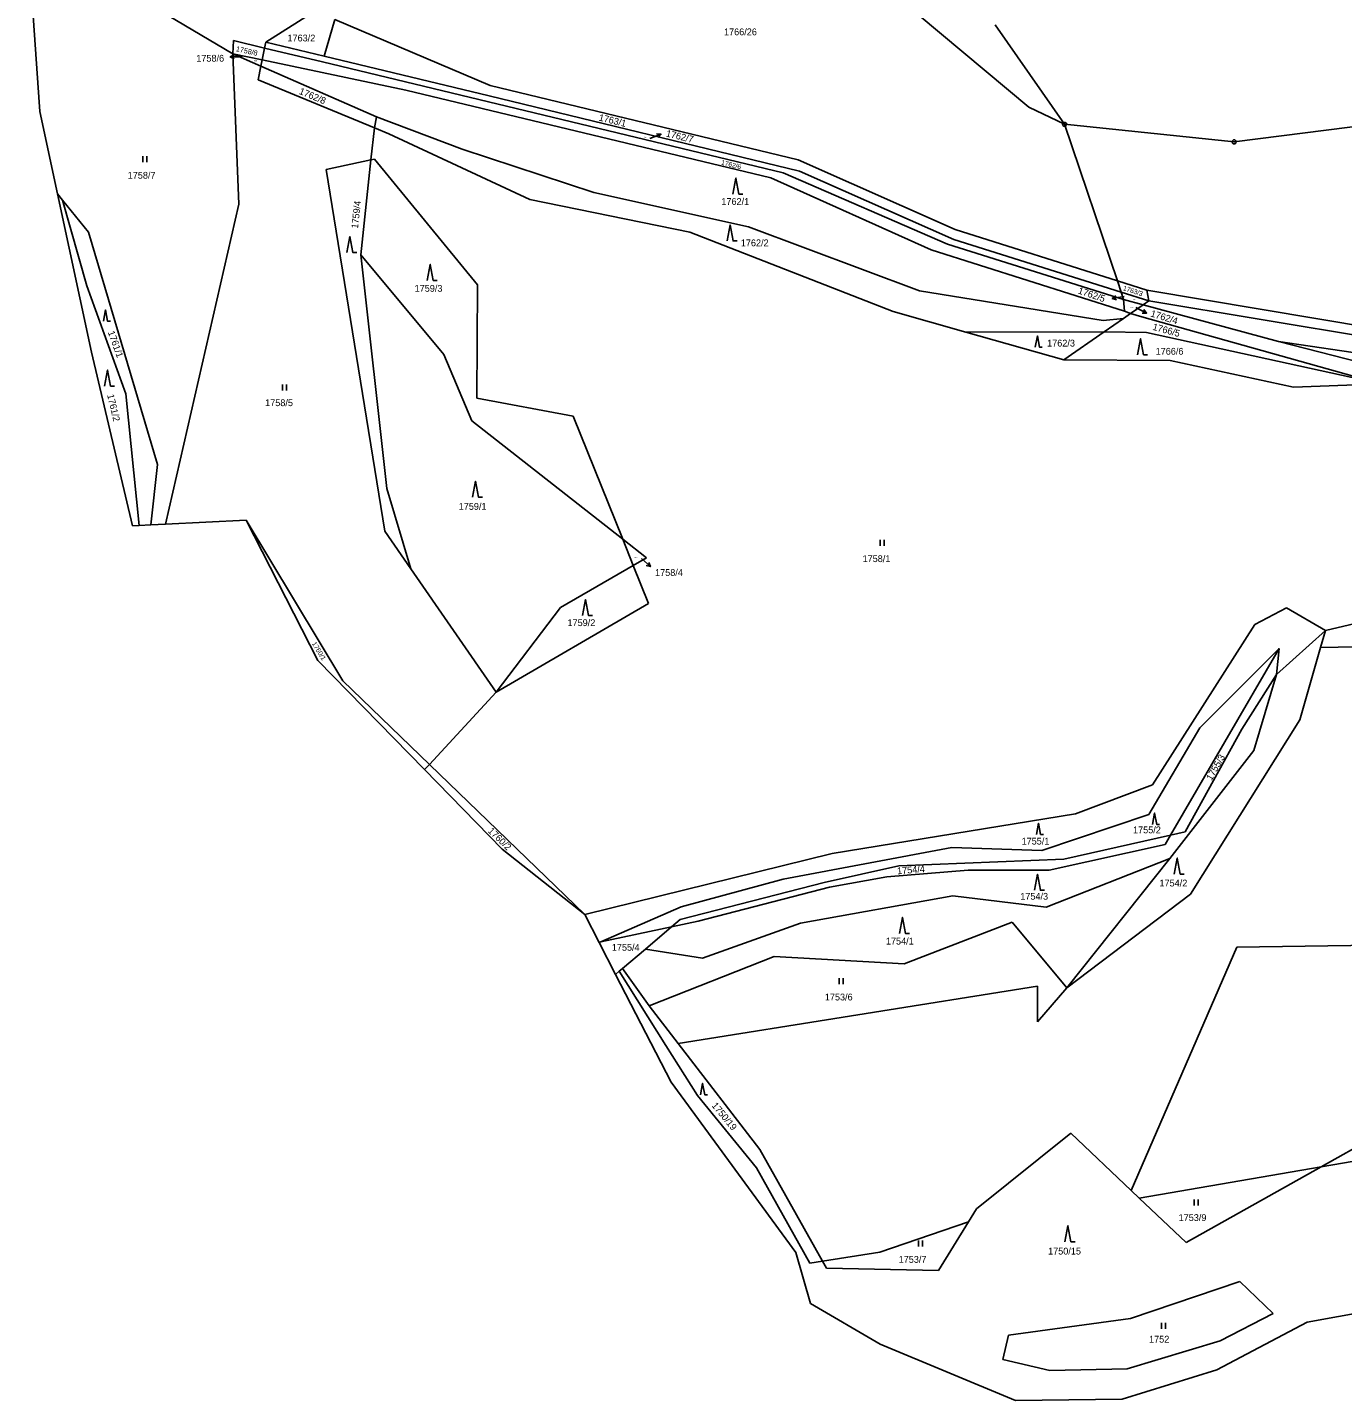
# Model space of a CAD drawing. Extents: x -609861 to -605046, y -1120287 to -1116307.
# Drawn here: x -609664.9 to -609336.2, y -1119535.1 to -1119191.9 of the extents above; entities that cross this region are included whole.
import ezdxf

# ---------------------------------------------------------------- set-up
doc = ezdxf.new("R2010")
doc.units = 0
for name, color, linetype in [('Vrstva 1', 7, 'Continuous'), ('Vrstva 2', 7, 'Continuous'), ('Vrstva 3', 7, 'Continuous'), ('Vrstva 7', 7, 'Continuous'), ('Vrstva 8', 7, 'Continuous')]:
    doc.layers.add(name, color=color, linetype=linetype)

msp = doc.modelspace()

# ---------------------------------------------------------------- linework, layer by layer
at = {"layer": 'Vrstva 1'}
for p, q in [((-609661.8, -1119212.92), (-609664.92, -1119167.98)), ((-609664.92, -1119167.98), (-609613.63, -1119198.48)), ((-609414.64, -1119211.82), (-609448.53, -1119183.44)), ((-609593.12, -1119187.81), (-609605.38, -1119195.59)), ((-609590.8, -1119199.1), (-609588.13, -1119189.92)), ((-609549.24, -1119206.37), (-609588.13, -1119189.92)), ((-609405.72, -1119216.1), (-609423.04, -1119191.27)), ((-609613.63, -1119198.48), (-609613.45, -1119195.16)), ((-609613.45, -1119195.16), (-609605.68, -1119197.03)), ((-609605.68, -1119197.03), (-609606.29, -1119200.02)), ((-609605.38, -1119195.59), (-609605.68, -1119197.03)), ((-609605.68, -1119197.03), (-609591.21, -1119200.52)), ((-609605.38, -1119195.59), (-609590.8, -1119199.1)), ((-609606.29, -1119200.02), (-609613.63, -1119198.48)), ((-609612.13, -1119236.03), (-609613.63, -1119198.48)), ((-609606.6, -1119201.55), (-609613.63, -1119198.48)), ((-609606.6, -1119201.55), (-609607.3, -1119204.98)), ((-609606.29, -1119200.02), (-609606.6, -1119201.55)), ((-609577.66, -1119214.2), (-609606.6, -1119201.55)), ((-609570.38, -1119207.57), (-609606.29, -1119200.02)), ((-609591.21, -1119200.52), (-609476.03, -1119228.22)), ((-609590.8, -1119199.1), (-609549.53, -1119209.02)), ((-609607.3, -1119204.98), (-609578.22, -1119216.98)), ((-609479.1, -1119229.5), (-609570.38, -1119207.57)), ((-609472.33, -1119224.95), (-609549.24, -1119206.37)), ((-609549.53, -1119209.02), (-609471.96, -1119227.83)), ((-609405.72, -1119216.1), (-609414.64, -1119211.82)), ((-609657.4, -1119233.49), (-609661.8, -1119212.92)), ((-609577.66, -1119214.2), (-609578.22, -1119216.98)), ((-609556.28, -1119222.29), (-609577.66, -1119214.2)), ((-609321.62, -1119215.22), (-609363.29, -1119220.5)), ((-609578.22, -1119216.98), (-609579.14, -1119225)), ((-609578.22, -1119216.98), (-609574.59, -1119218.48)), ((-609574.59, -1119218.48), (-609539.38, -1119234.87)), ((-609363.29, -1119220.5), (-609405.72, -1119216.1)), ((-609405.72, -1119216.1), (-609392.5, -1119255.26)), ((-609523.38, -1119233.14), (-609556.28, -1119222.29)), ((-609590.29, -1119227.36), (-609579.14, -1119225)), ((-609579.14, -1119225), (-609581.58, -1119248.69)), ((-609579.14, -1119225), (-609578.18, -1119224.8)), ((-609578.18, -1119224.8), (-609552.48, -1119256.21)), ((-609433.08, -1119242.36), (-609472.33, -1119224.95)), ((-609575.56, -1119317.81), (-609590.29, -1119227.36)), ((-609476.03, -1119228.22), (-609434.94, -1119246.1)), ((-609471.96, -1119227.83), (-609433.37, -1119244.9)), ((-609439.08, -1119247.52), (-609479.1, -1119229.5)), ((-609648.95, -1119273.02), (-609657.4, -1119233.49)), ((-609656.14, -1119235.05), (-609657.4, -1119233.49)), ((-609650.09, -1119256.46), (-609656.14, -1119235.05)), ((-609649.68, -1119243.03), (-609656.14, -1119235.05)), ((-609630.45, -1119316.07), (-609612.13, -1119236.03)), ((-609539.38, -1119234.87), (-609499.33, -1119243.06)), ((-609484.72, -1119241.7), (-609523.38, -1119233.14)), ((-609441.94, -1119257.69), (-609484.72, -1119241.7)), ((-609392.5, -1119255.26), (-609433.08, -1119242.36)), ((-609632.39, -1119301.13), (-609649.68, -1119243.03)), ((-609499.33, -1119243.06), (-609448.58, -1119262.88)), ((-609434.94, -1119246.1), (-609390.94, -1119259.87)), ((-609433.37, -1119244.9), (-609391.55, -1119258.05)), ((-609581.58, -1119248.69), (-609575.14, -1119307.11)), ((-609560.83, -1119273.68), (-609581.58, -1119248.69)), ((-609390.76, -1119262.85), (-609439.08, -1119247.52)), ((-609640.31, -1119283.44), (-609650.09, -1119256.46)), ((-609552.48, -1119256.21), (-609552.57, -1119284.59)), ((-609392.5, -1119255.26), (-609391.55, -1119258.05)), ((-609385.17, -1119257.59), (-609392.5, -1119255.26)), ((-609396.08, -1119265.11), (-609441.94, -1119257.69)), ((-609391.55, -1119258.05), (-609390.94, -1119259.87)), ((-609391.55, -1119258.05), (-609384.62, -1119260.23)), ((-609390.94, -1119259.87), (-609390.76, -1119262.85)), ((-609386.03, -1119261.2), (-609390.94, -1119259.87)), ((-609317.83, -1119268.81), (-609385.17, -1119257.59)), ((-609385.17, -1119257.59), (-609384.62, -1119260.23)), ((-609448.58, -1119262.88), (-609430.36, -1119268.04)), ((-609389.24, -1119263.43), (-609390.99, -1119264.64)), ((-609390.76, -1119262.85), (-609389.24, -1119263.43)), ((-609386.03, -1119261.2), (-609389.24, -1119263.43)), ((-609389.24, -1119263.43), (-609386.4, -1119264.22)), ((-609384.62, -1119260.23), (-609386.03, -1119261.2)), ((-609352.27, -1119270.37), (-609386.03, -1119261.2)), ((-609314.61, -1119271.87), (-609384.62, -1119260.23)), ((-609390.99, -1119264.64), (-609396.08, -1119265.11)), ((-609390.99, -1119264.64), (-609395.81, -1119267.98)), ((-609386.4, -1119264.22), (-609326.7, -1119280.96)), ((-609430.36, -1119268.04), (-609395.81, -1119267.98)), ((-609430.36, -1119268.04), (-609405.88, -1119274.96)), ((-609395.81, -1119267.98), (-609405.88, -1119274.96)), ((-609395.81, -1119267.98), (-609385.19, -1119268.16)), ((-609385.19, -1119268.16), (-609326.7, -1119280.96)), ((-609319.22, -1119278.92), (-609352.27, -1119270.37)), ((-609319.91, -1119275.12), (-609352.27, -1119270.37)), ((-609638.69, -1119316.5), (-609648.95, -1119273.02)), ((-609553.86, -1119290.23), (-609560.83, -1119273.68)), ((-609405.88, -1119274.96), (-609379.34, -1119275.16)), ((-609379.34, -1119275.16), (-609348.47, -1119281.81)), ((-609636.97, -1119316.41), (-609640.31, -1119283.44)), ((-609348.47, -1119281.81), (-609326.7, -1119280.96)), ((-609552.57, -1119284.59), (-609528.55, -1119289.02)), ((-609516.15, -1119319.84), (-609553.86, -1119290.23)), ((-609528.55, -1119289.02), (-609516.15, -1119319.84)), ((-609634.05, -1119316.26), (-609632.39, -1119301.13)), ((-609575.14, -1119307.11), (-609569.09, -1119327.19)), ((-609636.97, -1119316.41), (-609638.69, -1119316.5)), ((-609634.05, -1119316.26), (-609636.97, -1119316.41)), ((-609630.45, -1119316.07), (-609634.05, -1119316.26)), ((-609610.24, -1119315.03), (-609630.45, -1119316.07)), ((-609592.32, -1119350.12), (-609610.24, -1119315.03)), ((-609586.09, -1119355.21), (-609610.24, -1119315.03)), ((-609569.09, -1119327.19), (-609575.56, -1119317.81)), ((-609510.23, -1119324.49), (-609516.15, -1119319.84)), ((-609516.15, -1119319.84), (-609513.52, -1119326.39)), ((-609513.52, -1119326.39), (-609510.23, -1119324.49)), ((-609547.77, -1119358.09), (-609569.09, -1119327.19)), ((-609531.69, -1119336.9), (-609513.52, -1119326.39)), ((-609513.52, -1119326.39), (-609509.68, -1119335.93)), ((-609509.68, -1119335.93), (-609547.77, -1119358.09)), ((-609547.77, -1119358.09), (-609531.69, -1119336.9)), ((-609358.16, -1119341.17), (-609350.22, -1119336.99)), ((-609350.22, -1119336.99), (-609340.5, -1119342.66)), ((-609383.71, -1119381.22), (-609358.16, -1119341.17)), ((-609340.5, -1119342.66), (-609325.84, -1119339.14)), ((-609352.71, -1119353.62), (-609340.5, -1119342.66)), ((-609341.72, -1119346.92), (-609340.5, -1119342.66)), ((-609379.19, -1119393.77), (-609352.08, -1119347.1)), ((-609352.08, -1119347.1), (-609371.92, -1119367)), ((-609352.08, -1119347.1), (-609352.71, -1119353.62)), ((-609346.89, -1119365), (-609341.72, -1119346.92)), ((-609341.72, -1119346.92), (-609325.12, -1119346.62)), ((-609565.67, -1119377.42), (-609592.32, -1119350.12)), ((-609564.46, -1119376.12), (-609586.09, -1119355.21)), ((-609361.41, -1119367.3), (-609352.71, -1119353.62)), ((-609352.71, -1119353.62), (-609358.39, -1119372.63)), ((-609564.46, -1119376.12), (-609547.77, -1119358.09)), ((-609374.23, -1119408.56), (-609346.89, -1119365)), ((-609371.92, -1119367), (-609384.63, -1119388.66)), ((-609375.53, -1119392.95), (-609361.41, -1119367.3)), ((-609358.39, -1119372.63), (-609379.37, -1119399.6)), ((-609565.67, -1119377.42), (-609564.46, -1119376.12)), ((-609525.65, -1119413.64), (-609564.46, -1119376.12)), ((-609546.24, -1119397.33), (-609565.67, -1119377.42)), ((-609402.98, -1119388.46), (-609383.71, -1119381.22)), ((-609463.82, -1119398.35), (-609402.98, -1119388.46)), ((-609384.63, -1119388.66), (-609411.42, -1119397.67)), ((-609405.9, -1119399.79), (-609379.19, -1119393.77)), ((-609380.58, -1119396.17), (-609379.19, -1119393.77)), ((-609379.19, -1119393.77), (-609375.53, -1119392.95)), ((-609525.65, -1119413.64), (-609546.24, -1119397.33)), ((-609433.87, -1119396.92), (-609476.07, -1119404.81)), ((-609411.42, -1119397.67), (-609433.87, -1119396.92)), ((-609409.52, -1119402.55), (-609380.58, -1119396.17)), ((-609525.65, -1119413.64), (-609463.82, -1119398.35)), ((-609447.1, -1119401.48), (-609405.9, -1119399.79)), ((-609379.37, -1119399.6), (-609410.34, -1119411.8)), ((-609405.12, -1119431.96), (-609379.37, -1119399.6)), ((-609465.76, -1119405.61), (-609447.1, -1119401.48)), ((-609464.44, -1119406.81), (-609450.1, -1119404.18)), ((-609450.1, -1119404.18), (-609429.81, -1119402.55)), ((-609429.81, -1119402.55), (-609409.52, -1119402.55)), ((-609501.8, -1119414.88), (-609465.76, -1119405.61)), ((-609476.07, -1119404.81), (-609501.5, -1119411.69)), ((-609497.31, -1119415.32), (-609464.44, -1119406.81)), ((-609433.64, -1119408.97), (-609471.67, -1119415.78)), ((-609410.34, -1119411.8), (-609433.64, -1119408.97)), ((-609405.12, -1119431.96), (-609374.23, -1119408.56)), ((-609522.06, -1119420.61), (-609525.65, -1119413.64)), ((-609501.5, -1119411.69), (-609521.65, -1119420.46)), ((-609521.65, -1119420.46), (-609503.97, -1119416.73)), ((-609510.49, -1119422.27), (-609503.97, -1119416.73)), ((-609503.97, -1119416.73), (-609501.8, -1119414.88)), ((-609503.97, -1119416.73), (-609497.31, -1119415.32)), ((-609471.67, -1119415.78), (-609496.2, -1119424.58)), ((-609445.78, -1119425.94), (-609418.83, -1119415.56)), ((-609418.83, -1119415.56), (-609405.12, -1119431.96)), ((-609521.65, -1119420.46), (-609522.06, -1119420.61)), ((-609517.94, -1119428.61), (-609522.06, -1119420.61)), ((-609362.62, -1119421.84), (-609270.25, -1119420.36)), ((-609516.18, -1119427.11), (-609510.49, -1119422.27)), ((-609496.2, -1119424.58), (-609510.49, -1119422.27)), ((-609509.5, -1119436.43), (-609478.25, -1119424.17)), ((-609478.25, -1119424.17), (-609445.78, -1119425.94)), ((-609389.05, -1119482.61), (-609362.62, -1119421.84)), ((-609517.94, -1119428.61), (-609517.01, -1119427.82)), ((-609517.01, -1119427.82), (-609516.18, -1119427.11)), ((-609517.01, -1119427.82), (-609505.36, -1119446.35)), ((-609516.18, -1119427.11), (-609509.5, -1119436.43)), ((-609504.04, -1119455.57), (-609517.94, -1119428.61)), ((-609502.27, -1119445.85), (-609412.51, -1119431.56)), ((-609412.51, -1119431.56), (-609412.51, -1119440.48)), ((-609412.51, -1119440.48), (-609405.12, -1119431.96)), ((-609509.5, -1119436.43), (-609502.27, -1119445.85)), ((-609505.36, -1119446.35), (-609497.42, -1119458.92)), ((-609502.27, -1119445.85), (-609481.89, -1119472.39)), ((-609472.85, -1119498.12), (-609504.04, -1119455.57)), ((-609497.42, -1119458.92), (-609482.7, -1119476.94)), ((-609341.58, -1119476.71), (-609310.23, -1119459.13)), ((-609427.76, -1119487.23), (-609404.17, -1119468.3)), ((-609404.17, -1119468.3), (-609389.05, -1119482.61)), ((-609481.89, -1119472.39), (-609466.2, -1119500.29)), ((-609311.06, -1119471.48), (-609341.58, -1119476.71)), ((-609482.7, -1119476.94), (-609469.36, -1119500.78)), ((-609341.58, -1119476.71), (-609387.04, -1119484.51)), ((-609375.3, -1119495.62), (-609341.58, -1119476.71)), ((-609389.05, -1119482.61), (-609387.04, -1119484.51)), ((-609387.04, -1119484.51), (-609375.3, -1119495.62)), ((-609429.76, -1119490.47), (-609427.76, -1119487.23)), ((-609451.89, -1119498.08), (-609429.76, -1119490.47)), ((-609437.24, -1119502.6), (-609429.76, -1119490.47)), ((-609469.2, -1119510.92), (-609472.85, -1119498.12)), ((-609469.36, -1119500.78), (-609466.2, -1119500.29)), ((-609466.2, -1119500.29), (-609451.89, -1119498.08)), ((-609466.2, -1119500.29), (-609465.21, -1119502.06)), ((-609465.21, -1119502.06), (-609437.24, -1119502.6)), ((-609389.26, -1119514.61), (-609361.93, -1119505.41)), ((-609361.93, -1119505.41), (-609353.59, -1119513.38)), ((-609451.82, -1119521.03), (-609469.2, -1119510.92)), ((-609353.59, -1119513.38), (-609366.82, -1119520.2)), ((-609329.42, -1119512.7), (-609345.05, -1119515.51)), ((-609419.68, -1119518.81), (-609389.26, -1119514.61)), ((-609345.05, -1119515.51), (-609367.63, -1119527.48)), ((-609421.14, -1119524.91), (-609419.68, -1119518.81)), ((-609366.82, -1119520.2), (-609390.08, -1119527.21)), ((-609418.01, -1119535.14), (-609451.82, -1119521.03)), ((-609409.37, -1119527.61), (-609421.14, -1119524.91)), ((-609390.08, -1119527.21), (-609409.37, -1119527.61)), ((-609367.63, -1119527.48), (-609391.3, -1119534.77)), ((-609391.3, -1119534.77), (-609418.01, -1119535.14))]:
    msp.add_line(p, q, dxfattribs=at)
at = {"layer": 'Vrstva 3'}
for p, q in [((-609636.11, -1119224.07), (-609636.11, -1119225.57)), ((-609635.11, -1119225.57), (-609635.11, -1119224.07)), ((-609601.16, -1119281.12), (-609601.16, -1119282.62)), ((-609600.16, -1119282.62), (-609600.16, -1119281.12)), ((-609451.78, -1119320), (-609451.78, -1119321.5)), ((-609450.78, -1119321.5), (-609450.78, -1119320)), ((-609462.06, -1119429.53), (-609462.06, -1119431.03)), ((-609461.06, -1119431.03), (-609461.06, -1119429.53)), ((-609373.3, -1119484.91), (-609373.3, -1119486.41)), ((-609372.3, -1119486.41), (-609372.3, -1119484.91)), ((-609442.22, -1119495.17), (-609442.22, -1119496.67)), ((-609441.22, -1119496.67), (-609441.22, -1119495.17)), ((-609381.48, -1119515.74), (-609381.48, -1119517.24)), ((-609380.48, -1119517.24), (-609380.48, -1119515.74))]:
    msp.add_line(p, q, dxfattribs=at)
for points in [[(-609488.58, -1119233.55), (-609487.83, -1119229.55), (-609487.08, -1119233.55), (-609486.08, -1119233.55)], [(-609490.04, -1119245.25), (-609489.29, -1119241.25), (-609488.54, -1119245.25), (-609487.54, -1119245.25)], [(-609585.09, -1119248.17), (-609584.34, -1119244.17), (-609583.59, -1119248.17), (-609582.59, -1119248.17)], [(-609565.01, -1119255.12), (-609564.26, -1119251.12), (-609563.51, -1119255.12), (-609562.51, -1119255.12)], [(-609645.945, -1119265.32), (-609645.42, -1119262.52), (-609644.895, -1119265.32), (-609644.195, -1119265.32)], [(-609413.025, -1119271.8), (-609412.5, -1119269), (-609411.975, -1119271.8), (-609411.275, -1119271.8)], [(-609387.45, -1119273.69), (-609386.7, -1119269.69), (-609385.95, -1119273.69), (-609384.95, -1119273.69)], [(-609645.65, -1119281.52), (-609644.9, -1119277.52), (-609644.15, -1119281.52), (-609643.15, -1119281.52)], [(-609553.68, -1119309.35), (-609552.93, -1119305.35), (-609552.18, -1119309.35), (-609551.18, -1119309.35)], [(-609526.17, -1119338.91), (-609525.42, -1119334.91), (-609524.67, -1119338.91), (-609523.67, -1119338.91)], [(-609383.735, -1119391.1), (-609383.21, -1119388.3), (-609382.685, -1119391.1), (-609381.985, -1119391.1)], [(-609412.745, -1119393.63), (-609412.22, -1119390.83), (-609411.695, -1119393.63), (-609410.995, -1119393.63)], [(-609378.28, -1119403.54), (-609377.53, -1119399.54), (-609376.78, -1119403.54), (-609375.78, -1119403.54)], [(-609413.23, -1119407.59), (-609412.48, -1119403.59), (-609411.73, -1119407.59), (-609410.73, -1119407.59)], [(-609446.99, -1119418.36), (-609446.24, -1119414.36), (-609445.49, -1119418.36), (-609444.49, -1119418.36)], [(-609496.695, -1119458.68), (-609496.17, -1119455.88), (-609495.645, -1119458.68), (-609494.945, -1119458.68)], [(-609405.6, -1119495.44), (-609404.85, -1119491.44), (-609404.1, -1119495.44), (-609403.1, -1119495.44)]]:
    msp.add_lwpolyline(points, dxfattribs=at)
at = {"layer": 'Vrstva 7'}
for p, q in [((-609614.25, -1119199.261), (-609611.25, -1119199.26)), ((-609506.572, -1119218.569), (-609509.37, -1119219.65)), ((-609393.801, -1119259.632), (-609390.84, -1119259.15)), ((-609385.198, -1119263.294), (-609387.86, -1119261.91)), ((-609509.204, -1119326.645), (-609511.47, -1119324.68))]:
    msp.add_line(p, q, dxfattribs=at)
for points in [[(-609613.25, -1119199.76), (-609614.25, -1119199.261), (-609613.25, -1119198.76)], [(-609507.685, -1119218.463), (-609506.572, -1119218.569), (-609507.324, -1119219.396)], [(-609392.734, -1119259.965), (-609393.801, -1119259.632), (-609392.894, -1119258.977)], [(-609385.855, -1119262.389), (-609385.198, -1119263.294), (-609386.316, -1119263.276)], [(-609509.631, -1119325.613), (-609509.204, -1119326.645), (-609510.287, -1119326.368)]]:
    msp.add_lwpolyline(points, dxfattribs=at)
at = {"layer": 'Vrstva 8'}
for p, q in [((-609405.84, -1119216.1), (-609405.6, -1119216.1)), ((-609363.41, -1119220.5), (-609363.17, -1119220.5))]:
    msp.add_line(p, q, dxfattribs=at)
for points in [[(-609405.57, -1119215.62), (-609405.32, -1119215.8), (-609405.22, -1119216.09), (-609405.32, -1119216.38), (-609405.57, -1119216.56), (-609405.88, -1119216.56), (-609406.13, -1119216.38), (-609406.23, -1119216.09), (-609406.13, -1119215.8), (-609405.88, -1119215.62)], [(-609363.14, -1119220.02), (-609362.89, -1119220.2), (-609362.79, -1119220.49), (-609362.89, -1119220.78), (-609363.14, -1119220.96), (-609363.45, -1119220.96), (-609363.7, -1119220.78), (-609363.8, -1119220.49), (-609363.7, -1119220.2), (-609363.45, -1119220.02)]]:
    msp.add_lwpolyline(points, close=True, dxfattribs=at)

# ---------------------------------------------------------------- texts
at = {"layer": 'Vrstva 2'}
for s, height, p in [('1763/2', 1.7, (-609599.937, -1119195.38)), ('1766/26', 1.7, (-609490.827, -1119193.84)), ('1758/6', 0.2, (-609608.334, -1119200.34)), ('1758/7', 1.7, (-609639.867, -1119229.7)), ('1762/1', 1.7, (-609491.487, -1119236.25)), ('1762/2', 1.7, (-609486.627, -1119246.59)), ('1759/3', 1.7, (-609568.157, -1119257.96)), ('1762/5', 0.2, (-609388.654, -1119259.95)), ('1762/4', 0.2, (-609389.394, -1119261.96)), ('1762/3', 1.7, (-609410.067, -1119271.65)), ('1766/6', 1.7, (-609382.947, -1119273.69)), ('1758/5', 1.7, (-609605.517, -1119286.55)), ('1759/1', 1.7, (-609557.137, -1119312.47)), ('1758/4', 0.2, (-609513.234, -1119324.49)), ('1758/1', 1.7, (-609456.197, -1119325.54)), ('1759/2', 1.7, (-609529.947, -1119341.54)), ('1755/2', 1.7, (-609388.597, -1119393.33)), ('1755/1', 1.7, (-609416.457, -1119396.16)), ('1754/2', 1.7, (-609381.987, -1119406.63)), ('1754/3', 1.7, (-609416.777, -1119409.94)), ('1755/4', 1.7, (-609518.867, -1119422.7)), ('1754/1', 1.7, (-609450.367, -1119421.15)), ('1753/6', 1.7, (-609465.627, -1119435.12)), ('1753/9', 1.7, (-609377.207, -1119490.26)), ('1750/15', 1.7, (-609409.827, -1119498.64)), ('1753/7', 1.7, (-609447.177, -1119500.71)), ('1752', 1.7, (-609384.587, -1119520.66))]:
    msp.add_text(s, height=height, dxfattribs=at).set_placement(p)
for s, height, rotation, p in [('1758/8', 1.3, 347.38431, (-609612.907, -1119197.806)), ('1762/8', 1.7, 337.47214, (-609597.197, -1119208.46)), ('1763/1', 1.7, 346.52488, (-609522.248, -1119215.142)), ('1762/7', 0.2, 346.52488, (-609510.915, -1119219.371)), ('1762/6', 1.2, 346.52488, (-609491.64, -1119226.175)), ('1759/4', 1.7, 83.70913, (-609582.307, -1119242.24)), ('1763/3', 1.2, 341.99851, (-609391.206, -1119257.536)), ('1766/5', 1.7, 344.69141, (-609383.841, -1119267.454)), ('1761/1', 1.7, 289.80205, (-609644.857, -1119268.069)), ('1761/2', 1.7, 283.49952, (-609645.028, -1119283.762)), ('1760/1', 1.2, 301.49039, (-609593.885, -1119345.916)), ('1755/3', 1.7, 60.27516, (-609368.965, -1119380.279)), ('1760/2', 1.7, 315.87163, (-609549.978, -1119392.913)), ('1754/4', 1.7, 4.52637, (-609447.499, -1119403.599)), ('1750/19', 1.7, 309.62639, (-609494.02, -1119461.452))]:
    msp.add_text(s, height=height, rotation=rotation, dxfattribs=at).set_placement(p)
at = {"layer": 'Vrstva 7'}
for s, p in [('1758/6', (-609622.724, -1119200.44)), ('1758/4', (-609508.057, -1119329))]:
    msp.add_text(s, height=1.7, dxfattribs=at).set_placement(p)
for s, rotation, p in [('1762/7', 346.52488, (-609505.456, -1119219.128)), ('1762/5', 341.08178, (-609402.489, -1119258.341)), ('1762/4', 342.91524, (-609384.354, -1119264.1))]:
    msp.add_text(s, height=1.7, rotation=rotation, dxfattribs=at).set_placement(p)

doc.saveas('drawing.dxf')
